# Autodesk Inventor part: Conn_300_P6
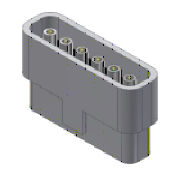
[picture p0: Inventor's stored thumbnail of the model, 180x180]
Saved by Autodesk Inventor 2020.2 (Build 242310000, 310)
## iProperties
Manager: www.cadconsulting.pl
Company: Fabian Stasiak CAD Consulting
IsCustomPart: 0
Created: 2014-10
Part Number: Conn_300_P6
Material: Ogólny
Description: Wtyk typ 300, ALPHA
Document SubType Name: Modeling
Standard: ALPHA 100/2012
Designer: F.Stasiak
Manufacturer: ALPHA
Standards Organization: ISO
Language: pl-PL
Size Designation: Conn_300_P6
Categories: <MemberInstance><Categories><Category DisplayName="Kable i wiązki przewodów" InternalName="e4a7e005-5e42-4d16-b293-125e7f0d0512" Mnemonic="CABLEANDHARNESS"><Cat
Density: 1 g/cm^3
Appearance: Śnieg
Catalog Web Link: www.expertbooks.pl
Author: F.Stasiak
Subject: Zbiór ćwiczeń. Autodesk Inventor 2020. Kurs Professional
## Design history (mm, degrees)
sketch "Szkic1"
  geometry: L1 (0, 0)-(30, 0); L2 (0, 2.5)-(30, 2.5); L3 (30, 2.5)-(30, -2.5); L4 (30, -2.5)-(0, -2.5); L5 (0, -2.5)-(0, 2.5); 7 further points
  constraints: 10 end point, 2 horizontal, 2 parallel, 1 coincident, 1 midpoint, 1 perpendicular
  dimensions: "d0" = 5 distance of point (7.5, 0) point (2.5, 0); "d1" = 5 distance of point (12.5, 0) point (7.5, 0) (= d0); "d2" = 5 distance of point (17.5, 0) point (12.5, 0) (= d0); "d3" = 5 distance of point (22.5, 0) point (17.5, 0) (= d0); "d4" = 5 distance of point (22.5, 0) point (27.5, 0) (= d0); "d16" = 2.5 distance of point (2.5, 0) L1.start; "d17" = 2.5 distance of point (27.5, 0) L1.end (= d16); "d18" = 5 distance of L4.end L2.start; "d19" = 30 distance of L3.end L4.end (= 0.5 x LPINÓW)
node "Oś konstrukcyjna1"
node "Oś konstrukcyjna2"
node "Oś konstrukcyjna3"
node "Oś konstrukcyjna4"
node "Oś konstrukcyjna5"
node "Oś konstrukcyjna6"
extrude "Wyciągnięcie proste3" new body sketch "Szkic1" distance "d20" = 3; taper "d21" = 0 deg
sketch "Szkic3"
  geometry: C1 r 1 at (2.5, 0); 2 further points
  constraints: 1 centre point, 1 coincident
  dimensions: "d22" = 2 diameter of C1
extrude "Wyciągnięcie proste4" join sketch "Szkic3" distance "d23" = 5; taper "d24" = 0 deg; dims "d29" = 15, "d30" = 0
sketch "Szkic4"
  geometry: C1 r 1.5 at (0, 0)
  constraints: 1 centre point
  dimensions: "d31" = 3 diameter of C1
extrude "Wyciągnięcie proste5" join sketch "Szkic4" stored distance "d32" = 0; taper "d33" = 0 deg
sketch "Szkic5"
  geometry: C1 r 0.9 at (0, 0)
  constraints: 1 centre point
  dimensions: "d34" = 1.8 diameter of C1
extrude "Wyciągnięcie proste6" cut sketch "Szkic5" distance "d35" = 7; taper "d36" = 0 deg
fillet "Zaokrąglenie3" dims "d45" = 1
pattern_linear "Szyk prostokątny2" dims "d27" = 5
node "Płaszczyzna konstrukcyjna1"
sketch "Szkic6"
  geometry: L1 (0, -2.5)-(30, -2.5) reference; L2 (30, -2.5)-(30, 2.5) reference; L3 (30, 2.5)-(0, 2.5) reference; L4 (0, 2.5)-(0, -2.5) reference; L5 (31.5, -4)-(-1.5, -4); L6 (-1.5, -4)-(-1.5, 4); L7 (-1.5, 4)-(31.5, 4); L8 (31.5, 4)-(31.5, -4)
  constraints: 8 end point, 3 other
  dimensions: "d37" = 1.5 distance between parallel lines of L5 L1
extrude "Wyciągnięcie proste7" join sketch "Szkic6" distance "d38" = 15.25; taper "d39" = 0 deg
fillet "Zaokrąglenie1" dims "d40" = 1
fillet "Zaokrąglenie2" dims "d41" = 2.5
chamfer "Faza1" distance "d42" = 1.05; stored, may be unused: second distance "d43" = 11, angle "d44" = 45 deg
sketch "Szkic7"
  geometry: L1 (-1.5, -1.5)-(-1.5, 1.5) reference; L2 (29, -4)-(1, -4) reference; L3 (31.5, 1.5)-(31.5, -1.5) reference; L4 (1, 4)-(29, 4) reference; L5 (-3, -1.5)-(-3, 1.5); L6 (1, 5.5)-(29, 5.5); L7 (33, 1.5)-(33, -1.5); L8 (29, -5.5)-(1, -5.5); C1 r 1.5 at (12.5, 0) reference; C2 r 1.5 at (7.5, 0) reference; C3 r 1.5 at (2.5, 0) reference; A1 r 2.5 centre (1, 1.5) between (1, 4) and (-1.5, 1.5) reference; A2 r 2.5 centre (1, -1.5) between (-1.5, -1.5) and (1, -4) reference; A3 r 2.5 centre (29, -1.5) between (29, -4) and (31.5, -1.5) reference; A4 r 2.5 centre (29, 1.5) between (31.5, 1.5) and (29, 4) reference; A5 r 4 centre (1, -1.5) between (-3, -1.5) and (1, -5.5); A6 r 4 centre (1, 1.5) between (1, 5.5) and (-3, 1.5); A7 r 4 centre (29, 1.5) between (33, 1.5) and (29, 5.5); A8 r 4 centre (29, -1.5) between (29, -5.5) and (33, -1.5)
  constraints: 8 end point, 8 point on circle, 4 centre point, 7 other
  dimensions: "d46" = 1.5 distance between parallel lines of L2 L8
extrude "Wyciągnięcie proste8" join sketch "Szkic7" stored distance "d47" = 12; taper "d48" = 0 deg
sketch "Szkic8"
  geometry: L1 (-1, 4)-(-29, 4) reference; L2 (1.5, -1.5)-(1.5, 1.5) reference; L3 (-29, -4)-(-1, -4) reference; L4 (-31.5, 1.5)-(-31.5, -1.5) reference; L5 (3, -1.5)-(3, 1.5) reference; L6 (-1, 5.5)-(-29, 5.5) reference; L7 (-33, 1.5)-(-33, -1.5) reference; L8 (-29, -5.5)-(-1, -5.5) reference; L9 (-12, -5.5)-(-18, -5.5); L10 (-18, -5.5)-(-18, -4); L11 (-18, -4)-(-12, -4); L12 (-12, -4)-(-12, -5.5); A1 r 2.5 centre (-1, 1.5) between (1.5, 1.5) and (-1, 4) reference; A2 r 2.5 centre (-1, -1.5) between (-1, -4) and (1.5, -1.5) reference; A3 r 2.5 centre (-29, -1.5) between (-31.5, -1.5) and (-29, -4) reference; A4 r 2.5 centre (-29, 1.5) between (-29, 4) and (-31.5, 1.5) reference; A5 r 4 centre (-1, -1.5) between (-1, -5.5) and (3, -1.5) reference; A6 r 4 centre (-1, 1.5) between (3, 1.5) and (-1, 5.5) reference; A7 r 4 centre (-29, 1.5) between (-29, 5.5) and (-33, 1.5) reference; A8 r 4 centre (-29, -1.5) between (-33, -1.5) and (-29, -5.5) reference; 2 further points
  constraints: 8 end point, 4 midpoint, 2 parallel, 1 horizontal, 1 perpendicular
  dimensions: "d49" = 6 distance of L9.start L9.end
extrude "Wyciągnięcie proste9" join sketch "Szkic8" distance "d50" = 6.5; taper "d51" = 0 deg
node "Punkt konstrukcyjny2"
node "Punkt konstrukcyjny3"
node "Punkt konstrukcyjny4"
node "Punkt konstrukcyjny5"
node "Punkt konstrukcyjny6"
node "Punkt konstrukcyjny7"
node "1"
node "2"
node "3"
node "4"
node "5"
node "6"
node "Bryła2"
node "Pętla rzutowana1"
node "Pętla rzutowana2"
other parameters: "d28" = 8
